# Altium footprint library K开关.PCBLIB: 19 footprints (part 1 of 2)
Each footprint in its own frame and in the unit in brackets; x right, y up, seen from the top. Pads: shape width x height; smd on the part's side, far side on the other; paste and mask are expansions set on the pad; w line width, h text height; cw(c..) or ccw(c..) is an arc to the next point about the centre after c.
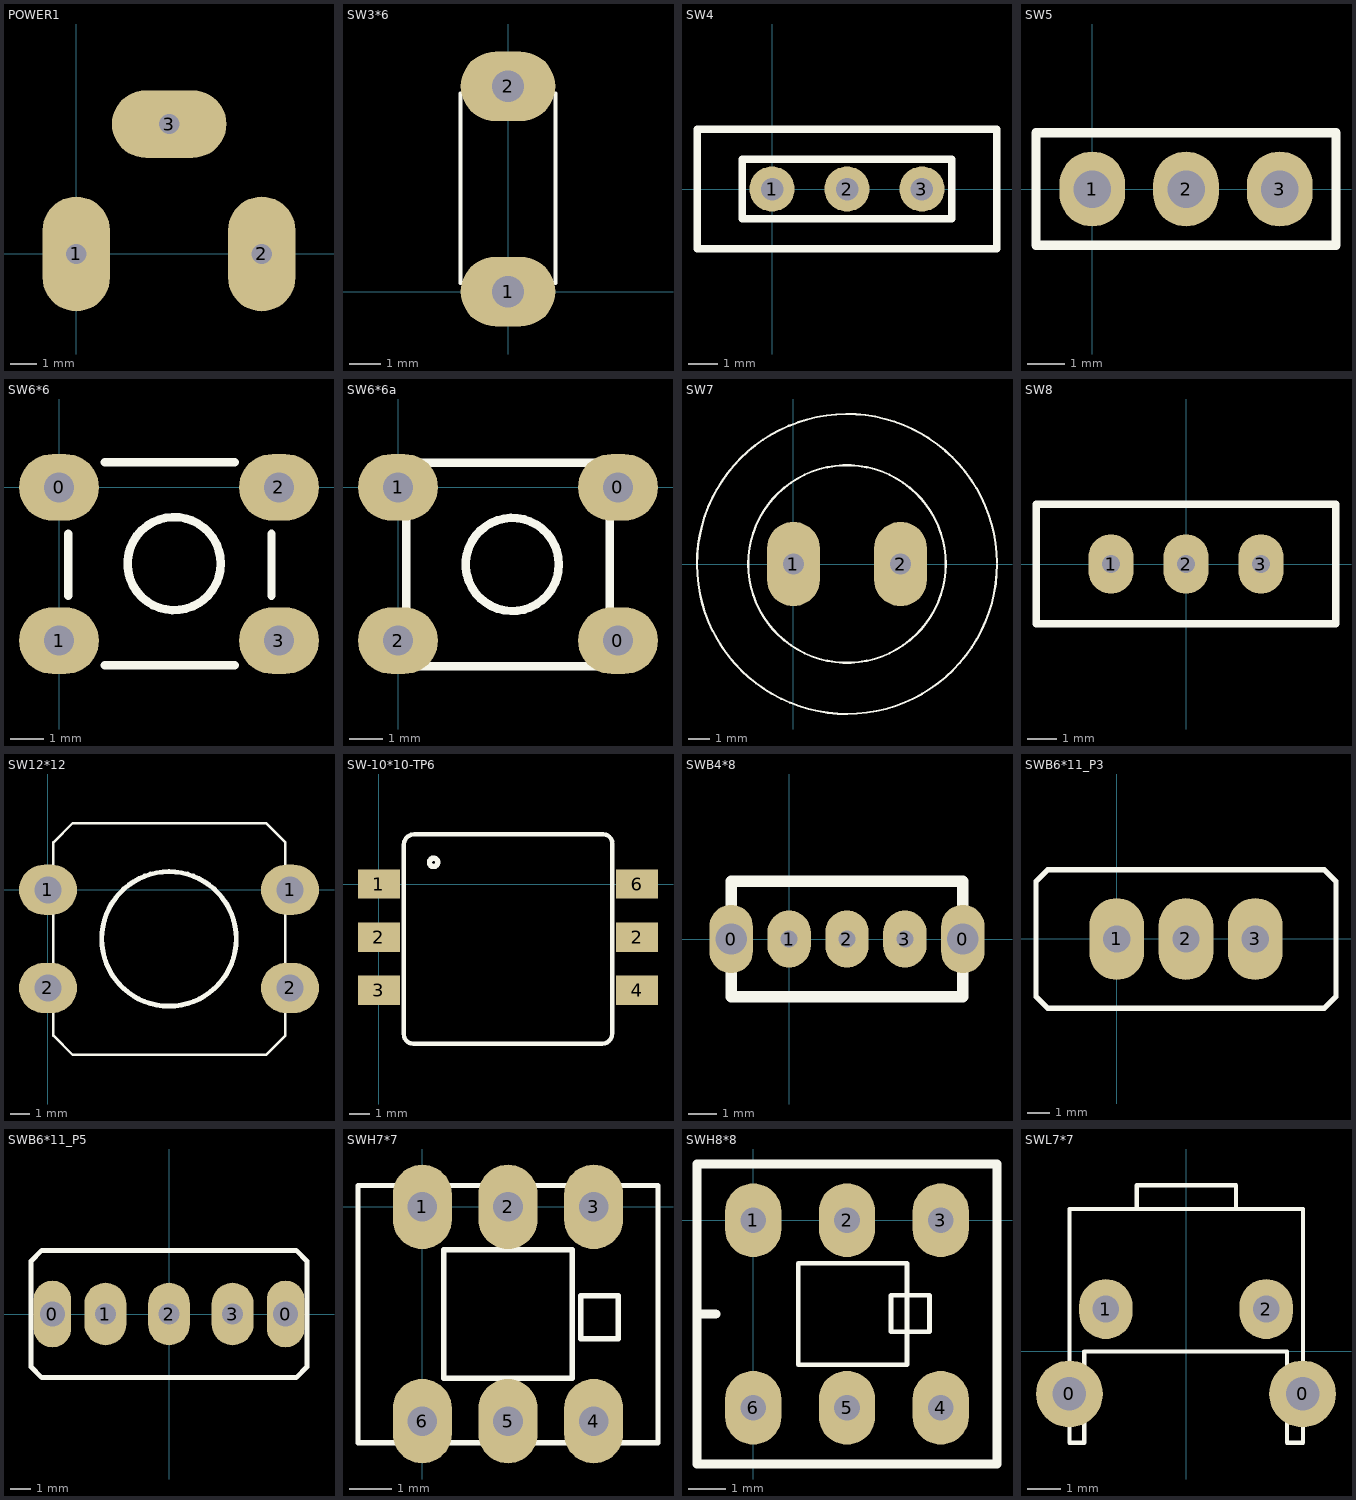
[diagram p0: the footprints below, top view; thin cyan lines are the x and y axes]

## POWER1 [mil]
pads (3):
  oval 100x170 hole 30: 1(0,0) 2(275,0)
  oval 170x100 hole 30: 3(137.8,192.68)

## SW3*6 [mm]
pads (2):
  oval 3x2.2 hole 1: 1(0,0) 2(0,6.5)
TopOverlay:
  lines w0.127: -1.499,0.279 -1.499,6.274 1.499,6.274 1.499,0.279 0,0.279 -1.499,0.279

## SW4 [mil]
pads (3):
  round 60 hole 30: 1(0,0) 2(100,0) 3(200,0)
TopOverlay:
  lines w10: -80,80 300,80 300,-80 -100,-80 -100,80 -60,80 ; -40,-40 240,-40 240,40 -40,40 -40,-40

## SW5 [mil]
pads (3):
  oval 70x80 hole 40: 1(0,0) 2(100,0) 3(200,0)
TopOverlay:
  lines w10: -60,-60 -60,60 260,60 260,-60 -60,-60

## SW6*6 [mm]
pads (4):
  oval 2.4x2 hole 0.9: 0(0,0) 1(0,-4.6) 2(6.6,0) 3(6.6,-4.6)
TopOverlay:
  circle w0.254: c3.454,-2.289 r1.397
  lines w0.254: 0.279,-3.251 0.279,-1.397 ; 1.379,-5.337 5.275,-5.337 ; 1.379,0.759 5.275,0.759 ; 6.375,-3.251 6.375,-1.397

## SW6*6a [mm]
pads (4):
  oval 2.4x2 hole 0.9: 0(6.6,-4.6) 0(6.6,0) 1(0,0) 2(0,-4.6)
TopOverlay:
  circle w0.254: c3.429,-2.314 r1.397
  lines w0.254: 0.254,-5.362 0.254,0.734 6.35,0.734 6.35,-5.362 0.254,-5.362

## SW7 [mm]
pads (2):
  oval 2.5x4 hole 1: 1(0,0) 2(5.08,0)
TopOverlay:
  circle w0.1: c2.54,0 r4.684
  lines w0.1: 9.652,0 cw(c2.54,0) 9.652,0.062

## SW8 [mm]
pads (3):
  oval 1.524x2 hole 0.6: 1(-2.54,0) 2(0,0) 3(2.54,0)
TopOverlay:
  lines w0.254: -5.08,-2.032 -5.08,2.032 5.08,2.032 5.08,-2.032 -5.08,-2.032

## SW12*12 [mm]
pads (4):
  oval 3x2.6 hole 1.4: 1(0,0) 1(12.522,0) 2(0,-5.08) 2(12.522,-5.08)
TopOverlay:
  circle w0.254: c6.261,-2.54 r3.48
  lines w0.127: 0.279,-7.546 1.279,-8.546 11.279,-8.546 12.279,-7.546 12.279,2.454 11.279,3.454 1.279,3.454 0.279,2.454 0.279,-7.546

## SW-10*10-TP6 [mm]
pads (6):
  rect 2x1.4 smd: 1(0,0) 2(0,-2.54) 2(12.37,-2.54) 3(0,-5.08) 4(12.37,-5.08) 6(12.37,0)
TopOverlay:
  circle w0.203: c11.176,2.057 r0
  circle w0.254: c2.619,1.041 r0.2
  lines w0.203: 1.194,1.88 cw(c1.702,1.88) 1.702,2.388 10.744,2.388 cw(c10.744,1.956) 11.176,1.956 11.176,-7.163 cw(c10.693,-7.163) 10.693,-7.645 1.651,-7.645 cw(c1.651,-7.188) 1.194,-7.188 1.194,1.905

## SWB4*8 [mm]
pads (5):
  oval 1.524x2.4 hole 1.1: 0(-2.032,0) 0(6.096,0)
  oval 1.524x2 hole 0.6: 1(0,0) 2(2.032,0) 3(4.064,0)
TopOverlay:
  lines w0.4: -2.032,-2.032 6.096,-2.032 6.096,2.032 -2.032,2.032 -2.032,0 -2.032,-2.032

## SWB6*11_P3 [mm] "单刀双掷"
pads (3):
  oval 2.4x3.6 hole 1.2: 1(0,0) 2(3.048,0) 3(6.096,0)
TopOverlay:
  lines w0.24: -3.556,-2.54 -3.556,2.54 -3.048,3.048 9.144,3.048 9.652,2.54 9.652,-2.54 9.144,-3.048 -3.048,-3.048 -3.556,-2.54

## SWB6*11_P5 [mm] "单刀双掷，带两固定脚"
pads (5):
  oval 1.8x3.2 hole 1.2: 0(-5.588,0) 0(5.588,0)
  oval 2x3 hole 1: 1(-3.048,0) 2(0,0) 3(3.048,0)
TopOverlay:
  lines w0.24: -6.604,-2.54 -6.096,-3.048 6.096,-3.048 6.604,-2.54 6.604,2.54 6.096,3.048 -6.096,3.048 -6.604,2.54 -6.604,-2.54

## SWH7*7 [mm]
pads (6):
  oval 1.4x2 hole 0.7: 1(0,0) 2(2.032,0) 3(4.064,0) 4(4.064,-5.08) 5(2.032,-5.08) 6(0,-5.08)
TopOverlay:
  lines w0.127: -1.524,-5.588 -1.524,0.508 5.588,0.508 5.588,-5.588 -1.524,-5.588 ; 0.508,-4.064 0.508,-1.016 3.556,-1.016 3.556,-4.064 0.508,-4.064 ; 3.759,-3.124 4.267,-3.124 4.648,-3.124 4.648,-2.108 4.47,-2.108 4.267,-2.108 3.759,-2.108 3.759,-3.124

## SWH8*8 [mm]
pads (6):
  oval 1.524x2 hole 0.7: 1(0,0) 2(2.54,0) 3(5.08,0) 4(5.08,-5.08) 5(2.54,-5.08) 6(0,-5.08)
TopOverlay:
  lines w0.127: 1.219,-3.734 1.219,-3.912 ; 1.219,-3.912 4.166,-3.912 4.166,-1.168 1.219,-1.168 1.219,-3.912 ; 3.734,-3.023 3.734,-2.032 4.775,-2.032 4.775,-3.023 3.734,-3.023
  lines w0.254: -1.524,-2.54 -1.016,-2.54 ; -1.524,-6.604 -1.524,1.524 6.604,1.524 6.604,-6.604 -1.524,-6.604

## SWL7*7 [mm]
pads (4):
  round 2 hole 1: 0(-3.492,-1.27) 0(3.492,-1.27)
  oval 1.6x1.8 hole 0.8: 1(-2.4,1.27) 2(2.4,1.27)
TopOverlay:
  lines w0.127: -1.473,4.267 -1.473,4.978 0,4.978 1.499,4.978 1.499,4.267 ; 2.692,0 -3.048,0 -3.048,-2.733 -3.492,-2.733 -3.492,4.267 3.508,4.267 3.508,-2.733 3.023,-2.733 3.023,0 ; 2.692,0 3.023,0 ; 2.692,0 3.023,0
